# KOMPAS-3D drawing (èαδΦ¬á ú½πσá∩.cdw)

Views: Вид 1
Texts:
  Крышка
  Андрей
  Noncommercial version
  Ra12,5
  Ra6.3
  Ra3.2
  Уклоны формовочные по ГОСТ 3212-80.
  Необработанные внутренние поверхности покрыть грунтовкой.
  СЧ15 ГОСТ 1412-85
  ДГТУ
  ОКМА-30.06.01.00.15-
Dimensions and other numbers on the sheet: 150; 210; 125; 40; 22; 1,5; 20; 0,02; 180; 6 отв.; 13; 0,8; 4; 1:2; 2; 0,45; 1; 0; 3; 5; 6; 7; 8; 9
